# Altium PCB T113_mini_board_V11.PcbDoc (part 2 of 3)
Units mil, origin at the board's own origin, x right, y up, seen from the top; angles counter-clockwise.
Board outline 2716.54 x 2716.54 mil, 4 copper layers (Top Layer, GND, PWR, Bottom Layer); 97 components, 127 nets, 497 pads, 287 vias.
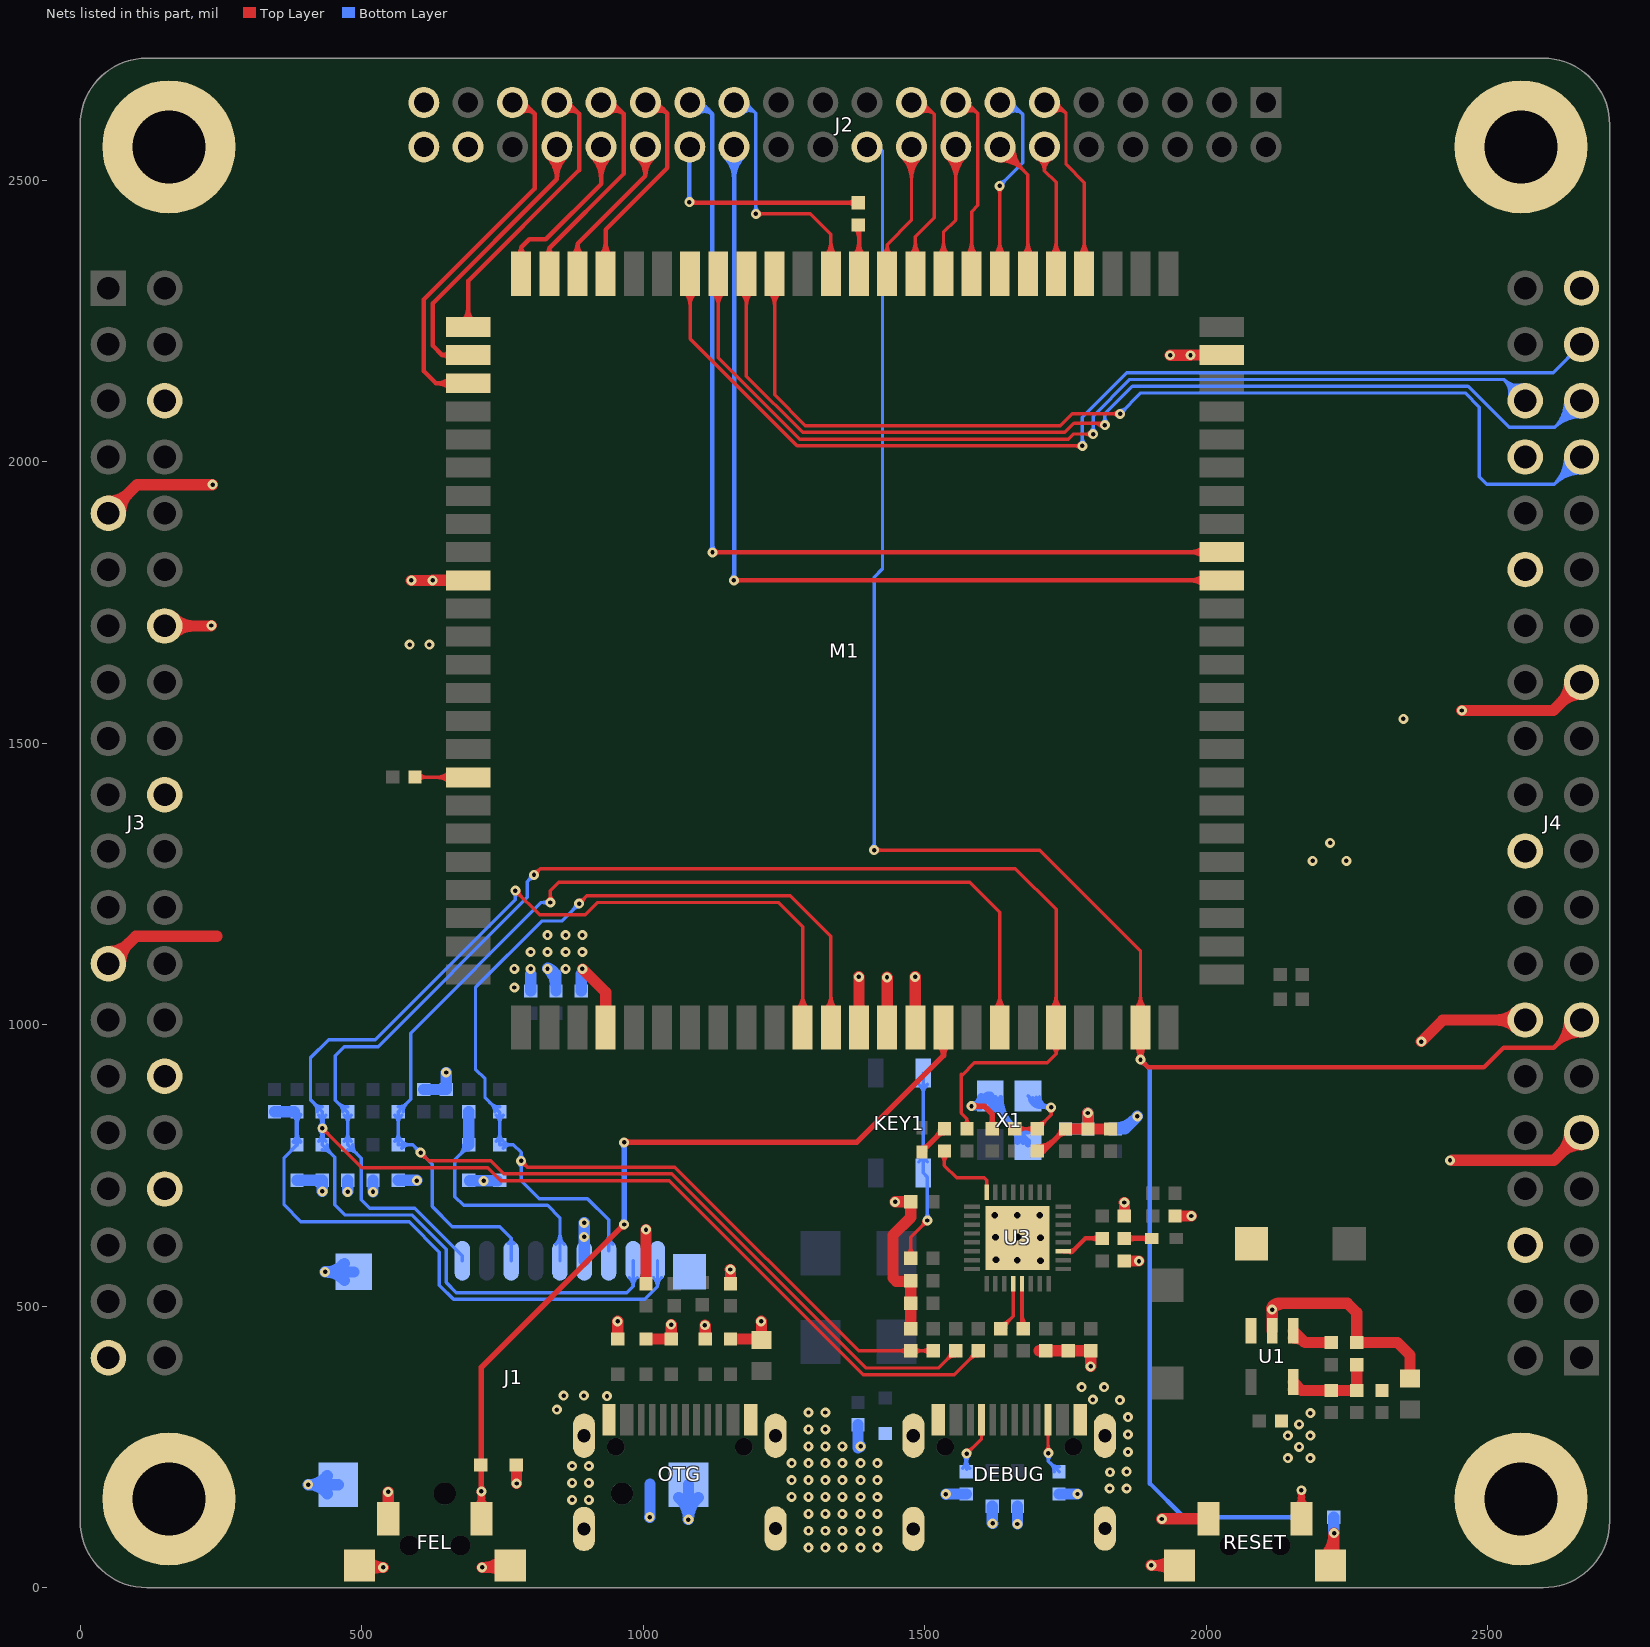
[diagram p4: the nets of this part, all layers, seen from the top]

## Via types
v1: diameter 17.72, hole 7.87, Top Layer to Bottom Layer, tented both sides, 278 vias
v2: diameter 23.62, hole 11.81, Top Layer to Bottom Layer, tented both sides, 9 vias

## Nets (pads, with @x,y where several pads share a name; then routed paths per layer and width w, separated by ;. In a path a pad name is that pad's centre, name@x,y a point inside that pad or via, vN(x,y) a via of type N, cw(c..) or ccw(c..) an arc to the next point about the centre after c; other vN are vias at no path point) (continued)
FEL: D4.2 FEL.2 M1.16 | length 1749.1
  Top Layer w10: FEL.2@702.21,142.47 ccw(c677.14,167.54) 712.59,167.54 ccw(c748.04,167.54) FEL.2@722.98,142.47 ; v1@709.25,169.07 cw(c698.54,162.89) 710.49,159.68 ; v1@709.86,168.27 cw(c703.28,161.69) 712.59,161.69 cw(c721.91,161.69) v1@715.32,168.27 ; v1@709.86,173.73 ccw(c703.28,180.31) 712.59,180.31 ccw(c721.91,180.31) v1@715.32,173.73 ; FEL.2@712.59,122.25 v1(712.59,171) 712.59,391.59 v1(966,645) ; 714.7,159.68 cw(c726.64,162.89) v1@715.93,169.07 ; v1@962.14,645 cw(c952.83,645) 959.41,638.41 cw(c966,631.83) v1@966,641.14 ; v1(966,791) 1379,791 1533.27,945.27 ; v1@968.73,788.27 cw(c975.31,781.69) 975.31,791 cw(c975.31,800.31) v1@968.73,793.73 ; M1.16@1524.9,963.69 cw(c1508.8,945.27) 1533.27,945.27 ; M1.16@1533.27,994.92 1533.27,945.27 ; M1.16@1541.63,963.69 ccw(c1557.73,945.27) 1533.27,945.27
  Bottom Layer w10: 704.03,125.03 ccw(c683.35,145.71) 712.59,145.71 ; 708.84,120.21 712.59,123.96 v1(712.59,171) ; v1@709.86,168.27 cw(c703.28,161.69) 712.59,161.69 cw(c721.91,161.69) v1@715.32,168.27 ; v1@963.27,647.73 ccw(c956.69,654.31) 966,654.31 ccw(c975.31,654.31) v1@968.73,647.73 ; v1@963.27,788.27 cw(c956.69,781.69) 966,781.69 cw(c975.31,781.69) v1@968.73,788.27 ; v1(966,645) v1(966,791)
GND: C1.1 C2.1 C3.1 C4.1 C6.1 C7.1 C8.1 C15.2 C16.2 C17.1 C18.1 C19.1 C20.1 C21.1 C22.1 C23.1 C24.1 C25.1 C26.1 C27.1 C28.1 C29.1 C30.1 C31.1 C32.1 C33.1 D4.1 D5.1 D6.1 D7.1 D8.1 D12.1 D13.1 D14.1 D15.1 D16.1 D17.1 D18.1 D19.1 D20.1 D21.1 D22.1 D23.1 DEBUG.A1B12 DEBUG.B1A12 DEBUG.SHELL FEL.1 FEL.3 FEL.4 J1.6 J1.10 J1.11 J1.12 J1.13 J2.38 J2.39 J2.40 J3.6 J3.9 J3.14 J3.20 J3.25 J3.30 J3.34 J3.39 J4.6 J4.9 J4.14 J4.20 J4.25 J4.30 J4.34 J4.39 M1.4 M1.13 M1.14 M1.15 M1.47 M1.82 OTG.A1B12 OTG.B1A12 OTG.SHELL pad.0 R6.2 R12.1 R13.1 R23.2 R24.2 R38.1 R39.2 RESET.1 RESET.3 RESET.4 U1.2 U3.33 X1.2 X1.4 | length 6477.8
  Top Layer w10: v1@1579.58,855.33 v1(1583,855.33) 1605.67,855.33 1619.92,841.08 C33.1@1619.92,814.99 ; v1@1585.73,852.6 cw(c1592.31,846.01) 1592.31,855.33 cw(c1592.31,864.64) v1@1585.73,858.05 ; C33.1@1615.1,819.8 ccw(c1603.48,831.43) 1619.92,831.43 ccw(c1636.36,831.43) C33.1@1624.74,819.8 ; U3.33@1664.93,621.15 v2(1664.93,622.74) ; C32.1@1699.92,772.43 ccw(c1699.92,791.15) 1713.16,777.91 ; C32.1@1699.92,775.62 1710.87,775.62 C27.1@1749.92,814.67 ; C32.1@1699.92,782.43 ccw(c1699.92,825.3) 1730.23,794.98 ; C27.1@1743.11,814.67 cw(c1726.67,814.67) 1738.29,803.05 cw(c1749.92,791.42) C27.1@1749.92,807.86
  Top Layer w20: J3.25@50,1108.27 98.73,1157 243,1157 ; J3.25@50,1129.76 ccw(c50,1181.66) 86.7,1144.96 ccw(c123.39,1108.27) J3.25@71.5,1108.27 ; J3.9@50,1908.27 100.73,1959 v1(235,1959) ; J3.9@50,1929.76 ccw(c50,1981.66) 86.7,1944.96 ccw(c123.39,1908.27) J3.9@71.5,1908.27 ; J3.14@150,1708.27 232.27,1708.27 v1(233,1709) ; J3.14@165.2,1693.07 cw(c201.9,1656.37) 201.9,1708.27 cw(c201.9,1760.16) J3.14@165.2,1723.47 ; FEL.3@491.48,35.96 v1@537.96,35.96 ; FEL.3@508.48,26.17 cw(c532.12,2.52) v1@532.12,35.96 ; FEL.3@509.79,49.53 ccw(c537.96,71.98) v1@537.96,35.96 ; v1(538,36) v1@537.96,35.96 ; FEL.1@540.38,138.94 ccw(c523.85,155.47) 547.23,155.47 ccw(c570.61,155.47) FEL.1@554.08,138.94 ; v1(547,170) 547.23,169.77 FEL.1@547.23,122.25 ; v1(588,1789) v1(626,1789) 626.21,1789.21 M1.82@688.98,1789.21 ; M1.82@661.87,1783.76 ccw(c648.69,1770.58) 648.69,1789.21 ccw(c648.69,1807.84) M1.82@661.87,1794.67 ; v1(714,36) 714.04,35.96 FEL.4@759.2,35.96 ; v1@715.06,35.96 ccw(c715.06,87.3) FEL.4@751.37,51 ; 727.72,35.96 cw(c727.72,2.52) FEL.4@751.37,26.17 ; v1(775,185) D4.1@775,217.5 ; v1(892,1099) 933.27,1057.73 M1.4@933.27,994.92 ; M1.4@927.81,1022.03 ccw(c914.64,1035.2) 933.27,1035.2 ccw(c951.9,1035.2) M1.4@938.72,1022.03 ; v1(954.58,473.09) 954.92,472.75 D6.1@954.92,441.8 ; D12.1@1004.92,441.8 D7.1@1049.92,441.8 1049.92,466.75 v1(1049.58,467.09) ; R12.1@1004.92,539.99 v1(1004.92,635.92) ; v1(1109.58,466.09) 1109.92,465.75 D8.1@1109.92,441.8 ; v1(1154.58,565.09) 1154.92,564.75 R13.1@1154.92,539.99 ; D13.1@1154.92,441.8 1207.82,441.8 C8.1@1209.88,439.74 1209.88,472.8 v1(1209.58,473.09) ; 1189.06,441.8 cw(c1189.06,420.89) C8.1@1203.84,435.67 ; M1.13@1377.81,1022.03 ccw(c1364.64,1035.2) 1383.27,1035.2 ccw(c1401.9,1035.2) M1.13@1388.72,1022.03 ; v1(1383,1085) 1383.27,1084.73 M1.13@1383.27,994.92 ; M1.14@1427.81,1022.03 ccw(c1414.64,1035.2) 1433.27,1035.2 ccw(c1451.9,1035.2) M1.14@1438.72,1022.03 ; v1(1433,1084) 1433.27,1083.73 M1.14@1433.27,994.92 ; v1(1447.58,685.09) 1447.8,685.3 C22.1@1475.24,685.3 1475.24,657.74 1443.58,626.09 1443.58,550.09 1449.58,544.09 1474.02,544.09 R39.2@1475.24,545.3 C24.1@1475.24,505.3 1474.92,504.99 R38.1@1474.92,459.99 ; M1.15@1477.81,1022.03 ccw(c1464.64,1035.2) 1483.27,1035.2 ccw(c1501.9,1035.2) M1.15@1488.72,1022.03 ; v1(1483,1085) 1483.27,1084.73 M1.15@1483.27,994.92 ; 1702.73,420.62 C18.1@1714.92,420.62 C20.1@1754.92,420.62 C23.1@1794.92,420.62 1794.92,393.43 v1(1794.58,393.09) ; C27.1@1749.92,814.67 C30.1@1789.92,814.67 ; v1(1789.58,843.09) 1789.92,842.75 C30.1@1789.92,814.67 ; C25.1@1829.92,814.67 C30.1@1789.92,814.67 ; C17.1@1854.61,580.3 1880.37,580.3 v1(1880.58,580.09) ; C19.1@1854.61,660.3 v1@1854.61,684.07 ; v1@1902,40 v1(1902.44,39.56) RESET.3@1952.75,39.56 ; v1(1921,122) 1921.24,122.24 RESET.1@2003.92,122.24 ; v1(1936,2189) v1(1972,2189) 1972.21,2189.21 M1.47@2027.56,2189.21 ; RESET.3@1940.34,27.15 ccw(c1910.36,-2.83) 1910.36,39.56 ccw(c1910.36,81.95) RESET.3@1940.34,51.98 ; C31.1@1944.61,660.3 1973.37,660.3 v1(1973.58,660.09) ; RESET.1@1997.08,115.39 ccw(c1980.54,98.86) 1980.54,122.24 ccw(c1980.54,145.62) RESET.1@1997.08,129.09 ; M1.47@2000.45,2183.76 ccw(c1987.28,2170.58) 1987.28,2189.21 ccw(c1987.28,2207.84) M1.47@2000.45,2194.67 ; v1@2115.87,494.12 cw(c2128,492.79) 2128,505 ; v1@2116.19,494.81 cw(c2140.8,470.2) 2140.8,505 ; U1.2@2117.21,456.08 2117.21,493.79 v1(2117,494) 2128,505 ; RESET.4@2208.32,53.22 ccw(c2166.36,97) v1(2227,97) 2227,46.09 RESET.4@2220.47,39.56 ; C6.1@2362,371.56 2362,413 2339.65,435.35 R6.2@2267.21,435.35 2267.21,488.79 2251,505 2128,505 ; v1(2382,970) 2420.27,1008.27 J4.14@2566.54,1008.27 ; v1@2437,759 2617.27,759 J4.9@2666.54,808.27 ; v1(2454,1558) 2616.27,1558 J4.25@2666.54,1608.27 ; J4.14@2551.34,993.07 ccw(c2514.64,956.37) 2514.64,1008.27 ccw(c2514.64,1060.16) J4.14@2551.34,1023.47 ; J4.9@2645.04,808.27 cw(c2593.14,808.27) 2629.84,771.57 cw(c2666.54,734.88) J4.9@2666.54,786.77 ; J4.25@2645.04,1608.27 cw(c2593.14,1608.27) 2629.84,1571.57 cw(c2666.54,1534.88) J4.25@2666.54,1586.77
  Bottom Layer w10: X1.4@1616.45,851.05 cw(c1616.45,828.91) 1632.11,844.57 ; X1.4@1616.45,860.22 1683.38,793.29 X1.2@1683.38,787 ; X1.4@1625.07,869.67 ccw(c1668.71,869.67) 1637.85,838.82 ; X1.4@1635.07,869.67 ccw(c1702.85,869.67) 1654.92,821.75 ; 1649.92,826.75 cw(c1614.11,790.93) X1.2@1664.76,790.93 ; 1655.62,821.05 ccw(c1683.38,848.82) X1.2@1683.38,809.55 ; X1.2@1666.99,809.68 cw(c1648.25,790.93) X1.2@1674.76,790.93
  Bottom Layer w15: v1@1583,856.68 ccw(c1583,896.58) X1.4@1611.21,868.37 ; X1.4@1600.4,871.17 cw(c1583,872.8) v1(1583,855.33) 1598.17,855.33 1613.19,870.35 X1.4@1616.45,873.61
  Bottom Layer w20: D14.1@385,723.5 D17.1@430,723.5 v1(430,704) ; v1(405,183) v1@405.09,182.91 ; v1(435,561) v1@435.14,560.86 ; J1.13@438.55,166.93 ccw(c405.09,139.89) v1@405.09,182.91 ; J1.13@438.55,198.9 cw(c405.09,225.93) v1@405.09,182.91 ; J1.13@458.34,182.91 v1@405.09,182.91 ; J1.11@469.26,545.75 ccw(c435.14,514.78) v1@435.14,560.86 ; J1.11@469.26,575.97 cw(c435.14,606.95) v1@435.14,560.86 ; v1@475,704 D16.1@475,723.5 ; J1.11@485.91,560.86 v1@435.14,560.86 ; v1(520,703) D15.1@520,723.5 ; D19.1@565,723.5 597.5,723.5 v1(598,723) ; C16.2@610,884.69 C15.2@650,884.69 v1(650,915) ; D20.1@691.34,722.72 v1(716.34,722.72) D18.1@741.34,722.72 ; C1.1@800,1059.68 800,1090 ; v1@830.26,1100.11 cw(c825.89,1081.51) 845,1081.51 ; v1@830.81,1099.81 cw(c796.54,1065.54) C3.1@845,1065.54 ; C3.1@845,1059.68 845,1090 ; C2.1@890,1059.68 890,1090 ; v1(895,648) 895,628 895.36,627.64 J1.6@895.36,580.55 ; v1(1011.58,125.09) 1011.92,125.43 1011.92,184 ; J1.12@1063.27,160.17 cw(c1027.95,121.4) v1@1080.4,121.4 ; v1(1080,121) v1@1080.4,121.4 ; J1.12@1080.4,182.91 v1@1080.4,121.4 ; J1.12@1097.53,160.17 ccw(c1132.85,121.4) v1@1080.4,121.4 ; v1@1381.58,248.09 C21.1@1381.58,289.41 ; 1381.58,258.91 ccw(c1393.91,258.91) v1@1385.19,250.19 ; v1@1384,253 v1(1386,251) ; v1(1537.58,166.09) 1537.9,166.41 R24.2@1573.58,166.41 ; X1.4@1612.45,871.09 X1.4@1613.19,870.35 ; D23.1@1619.92,144.59 1619.92,114.75 v1(1620.58,114.09) ; v1(1664.58,113.09) 1664.92,113.43 D22.1@1664.92,144.59 ; R23.2@1738.58,166.41 v1(1771.27,166.41) ; C28.1@1749.92,814.67 C29.1@1789.92,814.67 1789.92,842.75 v1(1789.58,843.09) ; C26.1@1838.58,814.78 1855.27,814.78 v1(1877.58,837.09) ; C26.1@1838.58,816.59 ccw(c1838.58,861.24) 1870.16,829.66 ; D5.1@2226.5,125 2226.5,97.5 v1(2227,97)
  other v1: 1293.58,71.09 1323.58,71.09 1353.58,71.09 1386,71 1416,71 1293.58,101.09 1323.58,101.09 1353.58,101.09 1386,101 1416,101 1293.58,131.09 1323.58,131.09 1353.58,131.09 1386,131 1416,131 873.58,156.09 903.58,156.09 1263.58,161.09 1293.58,161.09 1323.58,161.09 1353.58,161.09 1386,161 1416,161 1828.58,176.09 1858.58,176.09 873.58,186.09 903.58,186.09 1263.58,191.09 1293.58,191.09 1323.58,191.09 1353.58,191.09 1386,191 1416,191 1829,205 1858.58,206.09 873.58,216.09 903.58,216.09 1263.58,221.09 1293.58,221.09 1323.58,221.09 1353.58,221.09 1386,221 1416,221 2145,230 2185,230 1861,241 2165,250 1293.58,251.09 1323.58,251.09 1353.58,251.09 2145,270 2185,270 1861,272 1293.58,281.09 1323.58,281.09 2165,290 1861,303 2185,310 1293.58,311.09 1323.58,311.09 846.58,316.09 1846.58,333.09 1798.58,334.09 935.58,340.09 858.58,341.09 894.58,341.09 1778.58,356.09 1818.58,356.09 895,623 1854.58,684.09 475,703 2433,759 771,1066 771,1099 800,1099 830,1099 862,1099 800,1129 830,1129 862,1129 892,1129 830,1159 862,1159 892,1159 2189,1291 2249,1291 2220,1323 2350,1543 585,1675 620,1675
  other v2: 1705.58,580.67 1664.58,581.67 1626.58,582.67 1625.58,622.09 1705.58,621.67 1624.58,661.67 1664.58,661.67 1704.58,661.67
HPOUTFB: J2.35 M1.75 | length 810.8
  Top Layer w8: M1.75@657.62,2129.51 ccw(c634.21,2106.1) 634.21,2139.21 ccw(c634.21,2172.33) M1.75@657.62,2148.91 ; M1.75@688.98,2139.21 631.79,2139.21 610,2161 610,2288 807,2485 807,2618.19 ; J2.35@767.71,2657.48 807,2618.19 ; J2.35@772.47,2631.92 cw(c782.81,2619.14) 794.43,2630.76 ; J2.35@777.5,2625.7 cw(c788.43,2612.2) 800.71,2624.48 ; J2.35@782.54,2619.48 cw(c794.05,2605.25) 807,2618.2
HPOUTL: J2.34 M1.74 | length 712.4
  Top Layer w8: M1.74@655.58,2182.12 ccw(c643,2174.51) 643,2189.21 ; M1.74@655.58,2196.31 cw(c643,2203.92) 643,2189.21 ; M1.74@688.98,2189.21 643,2189.21 ; J2.34@829.8,2542.4 cw(c789.58,2502.18) 846.45,2502.18 cw(c903.33,2502.18) J2.34@863.11,2542.4 ; J2.34@835.45,2548.05 cw(c808.89,2521.49) 846.45,2521.49 cw(c884.02,2521.49) J2.34@857.46,2548.05 ; J2.34@846.45,2578.74 J2.34@846.45,2559.06 846.45,2501.45 626,2281 626,2206.21 643,2189.21
HPOUTR: J2.33 M1.73 | length 635.8
  Top Layer w8: M1.73@679.28,2248.91 ccw(c655.86,2272.33) 688.98,2272.33 ccw(c722.09,2272.33) M1.73@698.68,2248.91 ; M1.73@688.98,2249 688.98,2320.98 886,2518 886,2617.93 ; J2.33@846.45,2657.48 886,2617.93 ; J2.33@851.16,2631.88 cw(c861.53,2618.83) 873.32,2630.62 ; J2.33@856.14,2625.62 cw(c867.15,2611.76) 879.66,2624.28 ; J2.33@861.11,2619.35 cw(c872.76,2604.7) 886,2617.94
JTAG_TCK: D16.2 J1.1 M1.20 R19.2 R33.1 | length 2832.8
  Top Layer w6: v1(806,1266) 817,1277 1661,1277 1733.27,1204.73 M1.20@1733.27,994.92 1733.27,948 ; v1@806,1271.86 ccw(c806,1286) 816,1276 ccw(c826,1266) v1@811.86,1266 ; 1565,912 1566.5,910.5 ; R33.1@1569.49,821.93 ccw(c1560.76,833.08) 1574.92,833.08 ; R33.1@1574.92,814.99 1574.92,833.08 ; R33.1@1580.35,821.93 cw(c1589.09,833.08) 1574.92,833.08 ; M1.20@1722.86,1026.98 ccw(c1697.74,1052.1) 1733.27,1052.1 ccw(c1768.8,1052.1) M1.20@1743.67,1026.98 ; M1.20@1726.01,960.47 cw(c1718.94,948) 1733.27,948 ; M1.20@1727.1,1022.74 ccw(c1712.22,1037.62) 1733.27,1037.62 ccw(c1754.31,1037.62) M1.20@1739.43,1022.74 ; M1.20@1740.53,960.47 ccw(c1747.6,948) 1733.27,948 ; 1566.5,910.5 1588,932 1717.27,932 1733.27,948 ; 1566.5,910.5 1565,909 1565,843 1574.92,833.08
  Bottom Layer w6: 457.67,861.3 ccw(c475,878.63) R19.2@475,854.13 ; 460.91,858.07 cw(c448.15,845.31) R19.2@466.19,845.31 ; D16.2@468.77,792.73 ccw(c453.73,807.77) 475,807.77 ccw(c496.27,807.77) D16.2@481.23,792.73 ; R19.2@468.77,839.08 cw(c453.73,824.04) 475,824.04 cw(c496.27,824.04) R19.2@481.23,839.08 ; D16.2@475,777.68 cw(c475,755.08) 490.98,771.06 ; D16.2@475,786.5 475,843.98 453,865.98 453,945.03 468.97,961 529.12,961 794,1225.88 794,1254 v1(806,1266) ; D16.2@476.34,786.5 476.34,785.71 499,763.05 499,689 514,674 594.06,674 678.82,589.24 J1.1@678.82,580.55 ; D16.2@483.81,786.5 ccw(c503.75,786.5) 489.65,772.4 ; v1@800.14,1266 cw(c786,1266) 796,1256 cw(c806,1246) v1@806,1260.14
JTAG_TDI: D18.2 J1.7 M1.12 R21.2 R34.1 R38.2 | length 2867.7
  Top Layer w6: v1@783,752.14 cw(c783,738) 793,748 cw(c803,758) v1@788.86,758 ; v1(783,758) 794,747 1056,747 1382.38,420.62 R38.2@1474.92,420.62 R34.1@1514.92,420.62 ; v1(886,1215) 900,1229 1261,1229 1333.27,1156.73 M1.12@1333.27,994.92 ; v1@886,1220.86 ccw(c886,1235) 896,1225 ccw(c906,1215) v1@891.86,1215 ; M1.12@1322.86,1026.98 ccw(c1297.74,1052.1) 1333.27,1052.1 ccw(c1368.8,1052.1) M1.12@1343.67,1026.98 ; M1.12@1327.1,1022.74 ccw(c1312.22,1037.62) 1333.27,1037.62 ccw(c1354.31,1037.62) M1.12@1339.43,1022.74 ; R38.2@1468.69,414.39 ccw(c1453.65,399.35) 1453.65,420.62 ccw(c1453.65,441.89) R38.2@1468.69,426.85 ; R38.2@1481.15,414.39 cw(c1496.19,399.35) 1496.19,420.62 cw(c1496.19,441.89) R38.2@1481.15,426.85 ; R34.1@1508.69,414.39 ccw(c1493.65,399.35) 1493.65,420.62 ccw(c1493.65,441.89) R34.1@1508.69,426.85
  Bottom Layer w6: 727.67,861.3 ccw(c745,878.63) R21.2@745,854.13 ; 730.91,858.07 cw(c718.15,845.31) R21.2@736.19,845.31 ; D18.2@738.77,792.73 ccw(c723.73,807.77) 745,807.77 ccw(c766.27,807.77) 751.23,792.73 ccw(c766.27,807.77) 766.27,786.5 ccw(c766.27,765.22) D18.2@751.23,780.27 ; R21.2@738.77,839.08 cw(c723.73,824.04) 745,824.04 cw(c766.27,824.04) R21.2@751.23,839.08 ; v1@778.86,753.86 cw(c768.86,743.86) 783,743.86 cw(c797.14,743.86) v1@787.14,753.86 ; v1@778.86,762.14 ccw(c768.86,772.14) 783,772.14 ccw(c797.14,772.14) v1@787.14,762.14 ; v1@880.14,1215 cw(c866,1215) 876,1205 cw(c886,1195) v1@886,1209.14 ; v1(886,1215) 855,1184 820,1184 702,1066 702,921 719,904 719,869.98 745,843.98 D18.2@745,786.5 769.5,786.5 783,773 v1(783,758) 783,723 815,691 901,691 938.66,653.34 J1.7@938.66,598 ; J1.7@931.04,609.83 ccw(c912.63,628.23) 938.66,628.23 ccw(c964.68,628.23) J1.7@946.28,609.83
JTAG_TDO: D19.2 J1.3 M1.18 R22.2 R35.1 | length 3468.3
  Top Layer w6: v1@604.5,766.64 cw(c604.5,752.5) 614.5,762.5 cw(c624.5,772.5) v1@610.36,772.5 ; v1(604.5,772.5) 619,758 729,758 737.99,749.01 ; 737.97,749 751.97,735 1050.97,735 1395.88,390.09 1524.39,390.09 R35.1@1554.92,420.62 ; v1@830.86,1221.14 ccw(c820.86,1231.14) 835,1231.14 ccw(c849.14,1231.14) v1@839.14,1221.14 ; v1(835,1217) 835,1238 850,1253 1580,1253 1633.27,1199.73 M1.18@1633.27,994.92 M1.18@1633,994.65 ; R35.1@1546.11,420.62 cw(c1524.84,420.62) 1539.88,405.58 cw(c1554.92,390.54) R35.1@1554.92,411.81 ; M1.18@1622.86,1026.98 ccw(c1597.74,1052.1) 1633.27,1052.1 ccw(c1668.8,1052.1) M1.18@1643.67,1026.98 ; M1.18@1627.1,1022.74 ccw(c1612.22,1037.62) 1633.27,1037.62 ccw(c1654.31,1037.62) M1.18@1639.43,1022.74
  Bottom Layer w6: D19.2@558.77,792.73 ccw(c543.73,807.77) 565,807.77 ccw(c586.27,807.77) 571.23,792.73 ccw(c586.27,807.77) 586.27,786.5 ccw(c586.27,765.22) D19.2@571.23,780.27 ; R22.2@558.77,839.08 cw(c543.73,824.04) 565,824.04 cw(c586.27,824.04) R22.2@571.23,839.08 ; R22.2@565,845.31 587,867.31 587,984.94 819.06,1217 v1(835,1217) ; R22.2@565,854.13 ccw(c565,875.4) 580.04,860.36 ccw(c595.08,845.31) R22.2@573.81,845.31 ; R22.2@566.34,845.31 565,843.98 D19.2@565,786.5 590.5,786.5 v1(604.5,772.5) 625,752 625,677 661,641 745,641 765.43,620.57 ; v1@598.64,772.5 ccw(c584.5,772.5) 594.5,782.5 ccw(c604.5,792.5) v1@604.5,778.36 ; v1@604.5,766.64 cw(c604.5,752.5) 614.5,762.5 cw(c624.5,772.5) v1@610.36,772.5 ; J1.3@760.17,611.62 ccw(c755.18,620.57) 765.43,620.57 ; J1.3@765.43,580.55 765.43,620.57 ; J1.3@770.68,611.62 cw(c775.68,620.57) 765.43,620.57 ; v1@830.86,1212.86 ccw(c820.86,1202.86) 820.86,1217 ccw(c820.86,1231.14) v1@830.86,1221.14
JTAG_TMS: D17.2 J1.8 M1.11 R20.2 R36.1 | length 4026
  Top Layer w6: v1@430,810.14 cw(c430,796) 440,806 cw(c450,816) v1@435.86,816 ; v1(430,816) 500,746 724,746 747,723 1046,723 1390.91,378.09 1552.39,378.09 R36.1@1594.92,420.62 ; v1@773,1232.14 cw(c773,1218) 783,1228 cw(c793,1238) v1@778.86,1238 ; v1(773,1238) 816,1195 897,1195 919,1217 1240,1217 1283.27,1173.73 M1.11@1283.27,994.92 ; M1.11@1272.86,1026.98 ccw(c1247.74,1052.1) 1283.27,1052.1 ccw(c1318.8,1052.1) M1.11@1293.67,1026.98 ; M1.11@1277.1,1022.74 ccw(c1262.22,1037.62) 1283.27,1037.62 ccw(c1304.31,1037.62) M1.11@1289.43,1022.74 ; R36.1@1586.11,420.62 cw(c1564.84,420.62) 1579.88,405.58 cw(c1594.92,390.54) R36.1@1594.92,411.81
  Bottom Layer w6: R20.2@421.19,845.31 ccw(c399.92,845.31) 414.96,860.36 ccw(c430,875.4) R20.2@430,854.13 ; D17.2@423.77,792.73 ccw(c408.73,807.77) 430,807.77 ccw(c451.27,807.77) D17.2@436.23,792.73 ; R20.2@423.77,839.08 cw(c408.73,824.04) 430,824.04 cw(c451.27,824.04) R20.2@436.23,839.08 ; v1@425.53,812.22 cw(c415.81,803.99) 428.11,800.7 ; v1@425.53,819.78 ccw(c415.9,827.93) 428.08,831.2 ; v1@425.86,811.86 cw(c415.86,801.86) 430,801.86 cw(c444.14,801.86) v1@434.14,811.86 ; v1@425.86,820.14 ccw(c415.86,830.14) 430,830.14 ccw(c444.14,830.14) v1@434.14,820.14 ; v1@427.07,810.93 cw(c423.64,804.98) 430.27,806.76 ; v1@427.07,821.07 ccw(c423.55,827.17) 430.35,825.35 ; 429.65,825.35 ccw(c436.45,827.17) v1@432.93,821.07 ; 429.73,806.76 cw(c436.36,804.98) v1@432.93,810.93 ; D17.2@430,777.68 cw(c430,756.41) 445.04,771.45 cw(c460.08,786.5) D17.2@438.81,786.5 ; 431.89,800.7 cw(c444.19,803.99) v1@434.47,812.22 ; 431.92,831.2 ccw(c444.1,827.93) v1@434.47,819.78 ; v1@768.86,1233.86 cw(c758.86,1223.86) 773,1223.86 cw(c787.14,1223.86) v1@777.14,1233.86 ; v1(773,1238) 773,1221.85 524.15,973 441,973 409,941 409,866.31 R20.2@430,845.31 v1(430,816) D17.2@430,786.5 452,764.5 452,680 470,662 589.09,662 650,601.09 650,542 668,524 971,524 981.97,534.97 ; J1.8@974.83,550.82 cw(c960.8,534.97) 981.97,534.97 ; J1.8@981.97,580.55 981.97,534.97 ; J1.8@989.11,550.82 ccw(c1003.13,534.97) 981.97,534.97
LCD_D14: J2.11 M1.52 | length 522.5
  Top Layer w6: J2.11@1712.6,2657.48 1751,2619.08 ; J2.11@1721.04,2628.49 cw(c1731.3,2617.19) 1742.09,2627.98 ; J2.11@1725.07,2624.05 cw(c1735.53,2612.52) 1746.55,2623.53 ; J2.11@1729.1,2619.61 cw(c1739.77,2607.85) 1751,2619.08 ; J2.11@1737.16,2637.8 ccw(c1748.92,2637.8) 1740.6,2629.47 ; M1.52@1772.86,2365.56 ccw(c1747.74,2390.69) 1783.27,2390.69 ccw(c1818.8,2390.69) M1.52@1793.67,2365.56 ; M1.52@1777.1,2361.32 ccw(c1762.22,2376.2) 1783.27,2376.2 ccw(c1804.31,2376.2) M1.52@1789.43,2361.32 ; M1.52@1783.27,2333.5 1783.27,2495.73 1751,2528 1751,2619.08
LCD_D15: J2.12 M1.53 | length 412.6
  Top Layer w6: J2.12@1700.38,2537.75 cw(c1688.31,2516.67) 1712.6,2516.67 ; J2.12@1703.37,2542.95 cw(c1694.24,2527.03) 1712.6,2527.03 cw(c1730.95,2527.03) J2.12@1721.83,2542.95 ; J2.12@1712.6,2559.06 1712.6,2516.67 ; M1.53@1722.86,2365.56 ccw(c1697.74,2390.69) 1733.27,2390.69 ccw(c1768.8,2390.69) M1.53@1743.67,2365.56 ; J2.12@1724.81,2537.75 ccw(c1736.89,2516.67) 1712.6,2516.67 ; M1.53@1727.1,2361.32 ccw(c1712.22,2376.2) 1733.27,2376.2 ccw(c1754.31,2376.2) M1.53@1739.43,2361.32 ; M1.53@1733.27,2333.5 1733.27,2496 1712.6,2516.67
LCD_D18: J2.13 M1.55 | length 578.5
  Top Layer w6: M1.55@1622.86,2365.56 ccw(c1597.74,2390.69) 1633.27,2390.69 ccw(c1668.8,2390.69) M1.55@1643.67,2365.56 ; M1.55@1627.1,2361.32 ccw(c1612.22,2376.2) 1633.27,2376.2 ccw(c1654.31,2376.2) M1.55@1639.43,2361.32 ; v1@1628.86,2485.86 cw(c1618.21,2475.21) 1633.27,2475.21 ; v1(1633,2490) 1633.27,2489.73 M1.55@1633.27,2333.5 ; 1633.27,2476.5 cw(c1646.5,2476.5) v1@1637.14,2485.86
  Bottom Layer w6: v1(1633,2490) 1674,2531 1674,2617.34 ; v1@1633,2495.86 ccw(c1633,2510) 1643,2500 ccw(c1653,2490) v1@1638.86,2490 ; J2.13@1633.86,2657.48 1674,2617.34 ; J2.13@1641.73,2628.01 cw(c1652.46,2614.7) 1664.55,2626.79 ; J2.13@1645.5,2623.34 cw(c1656.67,2609.46) 1669.27,2622.06 ; J2.13@1649.26,2618.67 cw(c1660.89,2604.23) 1674,2617.34 ; J2.13@1658.42,2637.8 ccw(c1670.18,2637.8) 1661.86,2629.47
LCD_D19: J2.14 M1.54 | length 546
  Top Layer w6: J2.14@1633.86,2534.5 cw(c1633.86,2475.21) 1675.78,2517.13 cw(c1717.71,2559.06) J2.14@1658.42,2559.06 ; J2.14@1633.86,2540.5 cw(c1633.86,2495.69) 1665.54,2527.37 cw(c1697.22,2559.06) J2.14@1652.42,2559.06 ; J2.14@1633.86,2546.5 cw(c1633.86,2516.18) 1655.3,2537.62 cw(c1676.74,2559.06) J2.14@1646.42,2559.06 ; J2.14@1633.86,2559.06 1683.27,2509.64 M1.54@1683.27,2333.5 ; M1.54@1672.86,2365.56 ccw(c1647.74,2390.69) 1683.27,2390.69 ccw(c1718.8,2390.69) M1.54@1693.67,2365.56 ; M1.54@1677.1,2361.32 ccw(c1662.22,2376.2) 1683.27,2376.2 ccw(c1704.31,2376.2) M1.54@1689.43,2361.32
LCD_D20: J2.15 M1.56 | length 515.7
  Top Layer w6: J2.15@1555.12,2657.48 1594,2618.6 ; J2.15@1563.4,2628.36 cw(c1573.8,2616.51) 1584.94,2627.65 ; J2.15@1567.36,2623.85 cw(c1578.03,2611.69) 1589.47,2623.13 ; J2.15@1571.32,2619.34 cw(c1582.26,2606.86) 1594,2618.6 ; M1.56@1572.86,2365.56 ccw(c1547.74,2390.69) 1583.27,2390.69 ccw(c1618.8,2390.69) M1.56@1593.67,2365.56 ; M1.56@1577.1,2361.32 ccw(c1562.22,2376.2) 1583.27,2376.2 ccw(c1604.31,2376.2) M1.56@1589.43,2361.32 ; J2.15@1579.68,2637.8 ccw(c1591.44,2637.8) 1583.12,2629.47 ; M1.56@1583.27,2333.5 1583.27,2444.27 1594,2455 1594,2618.6
LCD_D21: J2.16 M1.57 | length 554.3
  Top Layer w6: M1.57@1522.86,2365.56 ccw(c1497.74,2390.69) 1533.27,2390.69 ccw(c1568.8,2390.69) M1.57@1543.67,2365.56 ; M1.57@1527.1,2361.32 ccw(c1512.22,2376.2) 1533.27,2376.2 ccw(c1554.31,2376.2) M1.57@1539.43,2361.32 ; M1.57@1533.27,2333.5 1533.27,2407.27 1555.12,2429.12 J2.16@1555.12,2578.74 ; J2.16@1537.75,2541.69 cw(c1495.83,2499.76) 1555.12,2499.76 cw(c1614.41,2499.76) J2.16@1572.48,2541.69 ; J2.16@1541.99,2545.93 cw(c1510.31,2514.25) 1555.12,2514.25 cw(c1599.92,2514.25) J2.16@1568.24,2545.93 ; J2.16@1546.24,2550.17 cw(c1524.8,2528.74) 1555.12,2528.74 cw(c1585.44,2528.74) J2.16@1564,2550.17
LCD_D22: J2.17 M1.58 | length 533.1
  Top Layer w6: M1.58@1472.86,2365.56 ccw(c1447.74,2390.69) 1483.27,2390.69 ccw(c1518.8,2390.69) M1.58@1493.67,2365.56 ; J2.17@1476.38,2657.48 1517,2616.86 ; M1.58@1477.1,2361.32 ccw(c1462.22,2376.2) 1483.27,2376.2 ccw(c1504.31,2376.2) M1.58@1489.43,2361.32 ; M1.58@1483.27,2333.5 1483.27,2399.27 1517,2433 1517,2616.86 ; J2.17@1484.1,2627.89 cw(c1494.94,2614) 1507.4,2626.46 ; J2.17@1487.79,2623.16 cw(c1499.14,2608.6) 1512.2,2621.66 ; J2.17@1491.48,2618.43 cw(c1503.35,2603.21) 1517,2616.86 ; J2.17@1500.94,2637.8 ccw(c1512.7,2637.8) 1504.38,2629.47
LCD_D23: J2.18 M1.59 | length 542.1
  Top Layer w6: M1.59@1424.23,2366.77 ccw(c1409.83,2385.27) 1433.27,2385.27 ; M1.59@1427.91,2362.04 ccw(c1419.38,2372.99) 1433.27,2372.99 ccw(c1447.15,2372.99) M1.59@1438.62,2362.04 ; M1.59@1433.27,2333.5 1433.27,2385.27 ; M1.59@1442.31,2366.77 cw(c1456.71,2385.27) 1433.27,2385.27 ; J2.18@1459.01,2541.69 cw(c1417.09,2499.76) 1476.38,2499.76 cw(c1535.67,2499.76) J2.18@1493.74,2541.69 ; J2.18@1463.25,2545.93 cw(c1431.57,2514.25) 1476.38,2514.25 cw(c1521.18,2514.25) J2.18@1489.5,2545.93 ; J2.18@1467.5,2550.17 cw(c1446.06,2528.74) 1476.38,2528.74 cw(c1506.7,2528.74) J2.18@1485.26,2550.17 ; J2.18@1476.38,2578.74 1476.38,2428.38 1433.27,2385.27
LCD_DE: J2.25 M1.61 | length 666.4
  Top Layer w6: v1(1200,2440) 1297,2440 1333.27,2403.73 M1.61@1333.27,2333.5 ; v1@1204.14,2435.86 cw(c1214.14,2425.86) 1214.14,2440 cw(c1214.14,2454.14) v1@1204.14,2444.14 ; M1.61@1322.86,2365.56 ccw(c1297.74,2390.69) 1333.27,2390.69 ccw(c1368.8,2390.69) M1.61@1343.67,2365.56 ; M1.61@1327.1,2361.32 ccw(c1312.22,2376.2) 1333.27,2376.2 ccw(c1354.31,2376.2) M1.61@1339.43,2361.32
  Bottom Layer w6: J2.25@1161.42,2657.48 1200,2618.9 ; J2.25@1169.8,2628.44 cw(c1180.11,2616.93) 1191.04,2627.86 ; J2.25@1173.8,2623.97 cw(c1184.35,2612.21) 1195.52,2623.38 ; J2.25@1177.8,2619.5 cw(c1188.58,2607.48) 1200,2618.9 ; J2.25@1185.97,2637.8 ccw(c1197.74,2637.8) 1189.42,2629.47 ; v1@1195.86,2444.14 ccw(c1185.86,2454.14) 1200,2454.14 ccw(c1214.14,2454.14) v1@1204.14,2444.14 ; v1(1200,2440) 1200,2618.9
LCD_HSYNC: J2.27 M1.40 | length 1908.9
  Top Layer w8: v1(1123,1839) 1123.21,1839.21 M1.40@2027.56,1839.21 ; v1@1126.44,1835.56 cw(c1135.24,1826.76) 1135.24,1839.21 ; v1@1126.44,1842.44 ccw(c1134.22,1850.22) 1134.22,1839.21 ; M1.40@1996.21,1829.51 ccw(c1972.79,1806.1) 1972.79,1839.21 ccw(c1972.79,1872.33) M1.40@1996.21,1848.91
  Bottom Layer w8: J2.27@1082.68,2657.48 1123,2617.16 ; J2.27@1087.23,2631.76 cw(c1097.69,2617.88) 1109.99,2630.17 ; J2.27@1092.04,2625.37 cw(c1103.29,2610.46) 1116.49,2623.66 ; J2.27@1096.86,2618.98 cw(c1108.88,2603.04) 1123,2617.16 ; v1@1119.56,1842.44 ccw(c1111.27,1850.73) 1123,1850.73 ccw(c1134.73,1850.73) v1@1126.44,1842.44 ; v1(1123,1839) 1123,2617.16
LCD_PCLK: J2.28 R4.2 | length 479.3
  Top Layer w8: v1(1082,2461) 1083.31,2459.69 R4.2@1382,2459.69 ; v1@1085.44,2464.44 ccw(c1096.9,2475.9) 1096.9,2459.69 ; R4.2@1376.48,2454.16 ccw(c1363.14,2440.83) 1363.14,2459.69 ccw(c1363.14,2478.54) R4.2@1376.48,2465.21
  Bottom Layer w8: v1@1078.56,2464.44 ccw(c1070.27,2472.73) 1082,2472.73 ccw(c1093.73,2472.73) v1@1085.44,2464.44 ; v1(1082,2461) 1082,2578.06 J2.28@1082.68,2578.74
LCD_RESET: D5.2 J2.20 J4.13 M1.23 RESET.2 | length 4618.3
  Top Layer w6: v1(1410,1310) 1704,1310 1883.27,1130.73 M1.23@1883.27,994.92 M1.23@1883.27,988 ; v1@1414.14,1305.86 cw(c1424.14,1295.86) 1424.14,1310 cw(c1424.14,1324.14) v1@1414.14,1314.14 ; M1.23@1872.86,1026.98 ccw(c1847.74,1052.1) 1883.27,1052.1 ccw(c1918.8,1052.1) M1.23@1893.67,1026.98 ; M1.23@1877.1,1022.74 ccw(c1862.22,1037.62) 1883.27,1037.62 ccw(c1904.31,1037.62) M1.23@1889.43,1022.74
  Top Layer w8: M1.23@1873.57,963.57 cw(c1850.15,940.15) 1883.27,940.15 cw(c1916.38,940.15) M1.23@1892.97,963.57 ; v1@1879.06,940.16 ccw(c1867.05,947.1) 1880.45,950.68 ; v1@1879.83,941.17 ccw(c1871.54,949.46) 1883.27,949.46 ccw(c1895,949.46) v1@1886.7,941.17 ; v1@1880.84,941.94 ccw(c1876.04,950.24) 1885.31,947.76 ; 1881.23,947.76 ccw(c1890.49,950.24) v1@1885.7,941.94 ; v1@1883.27,932.87 cw(c1883.27,921.15) 1891.56,929.44 cw(c1899.85,937.73) v1@1888.13,937.73 ; M1.23@1883.27,988 v1(1883.27,937.73) 1897,924 2493,924 2528,959 2617.27,959 J4.13@2666.54,1008.27 ; 1886.09,950.68 ccw(c1899.48,947.1) v1@1887.47,940.16 ; RESET.2@2158.19,143.18 ccw(c2131.42,169.95) 2169.28,169.95 ccw(c2207.15,169.95) RESET.2@2180.38,143.18 ; v1@2164.79,170.57 cw(c2151.49,162.89) 2166.33,158.92 ; v1@2165.56,169.56 cw(c2156.59,160.59) 2169.28,160.59 ; v1@2166.57,168.79 cw(c2161.58,160.16) 2171.22,162.74 ; 2167.66,163.88 cw(c2175.48,161.78) v1@2171.43,168.79 ; v1(2169,173) 2169.28,172.72 RESET.2@2169.28,122.24 ; 2169.28,161.96 cw(c2180.04,161.96) v1@2172.44,169.56 ; 2171.86,160.34 cw(c2184.89,163.83) v1@2173.21,170.57 ; J4.13@2639.04,1008.27 cw(c2572.66,1008.27) 2619.6,961.33 cw(c2666.54,914.39) J4.13@2666.54,980.77 ; J4.13@2647.04,1008.27 cw(c2599.97,1008.27) 2633.25,974.99 cw(c2666.54,941.7) J4.13@2666.54,988.77
  Bottom Layer w6: J2.20@1397.64,2578.74 1425,2551.38 1425,1810 1410,1795 v1(1410,1310) ; v1@1405.86,1314.14 ccw(c1395.86,1324.14) 1410,1324.14 ccw(c1424.14,1324.14) v1@1414.14,1314.14
  Bottom Layer w8: v1@1883.27,932.87 cw(c1883.27,921.15) 1891.56,929.44 cw(c1899.85,937.73) v1@1888.13,937.73 ; v1(1883.27,937.73) 1900,921 1900,185 1960,125 D5.2@2163.5,125 2169,130.5 v1(2169,173) ; D5.2@2157.98,119.48 ccw(c2144.65,106.14) 2144.65,125 ccw(c2144.65,143.86) D5.2@2157.98,130.52 ; v1@2165.56,169.56 cw(c2157.27,161.27) 2169,161.27 cw(c2180.73,161.27) v1@2172.44,169.56
LCD_VSYNC: J2.26 M1.39 | length 1893.6
  Top Layer w8: v1(1161,1789) 1161.21,1789.21 M1.39@2027.56,1789.21 ; v1@1164.44,1785.56 cw(c1173.24,1776.76) 1173.24,1789.21 ; v1@1164.44,1792.44 ccw(c1172.22,1800.22) 1172.22,1789.21 ; M1.39@1996.21,1779.51 ccw(c1972.79,1756.1) 1972.79,1789.21 ccw(c1972.79,1822.33) M1.39@1996.21,1798.91
  Bottom Layer w8: J2.26@1144.76,2542.4 cw(c1104.54,2502.18) 1161.42,2502.18 cw(c1218.29,2502.18) J2.26@1178.07,2542.4 ; J2.26@1150.41,2548.05 cw(c1123.85,2521.49) 1161.42,2521.49 cw(c1198.98,2521.49) J2.26@1172.42,2548.05 ; v1@1157.56,1792.44 ccw(c1148.27,1801.73) 1161.42,1801.73 ; v1@1161.42,1789 J2.26@1161.42,2578.74 ; 1161.42,1799.73 ccw(c1171.73,1799.73) v1@1164.44,1792.44
LED0: R29.1 U3.11 | length 128.9
  Top Layer w8: U3.11@1745.91,597.53 1762.58,597.53 ; U3.11@1755.7,597.49 ccw(c1759.12,600.99) 1762.58,597.53 ; U3.11@1755.75,597.47 ccw(c1755.75,613.82) 1767.31,602.26 ; R29.1@1809.71,614.78 ccw(c1796.38,601.45) 1796.38,620.3 ccw(c1796.38,639.16) R29.1@1809.71,625.83 ; R29.1@1815.24,620.3 1785.35,620.3 1762.58,597.53
LED1: R28.1 U3.24 | length 166.6
  Top Layer w6: R28.1@1528.69,769.39 cw(c1513.65,754.35) 1534.92,754.35 cw(c1556.19,754.35) R28.1@1541.15,769.39 ; R28.1@1534.92,775.62 1534.92,749.75 1556.58,728.09 1605.48,728.09 1609.81,723.76 U3.24@1609.81,702.13
LINEINL: J2.30 M1.70 | length 470.1
  Top Layer w8: M1.70@873.78,2365.07 ccw(c852.55,2387.27) 883.27,2387.27 ; M1.70@883.27,2333.5 883.27,2387.27 ; M1.70@892.75,2365.07 cw(c913.99,2387.27) 883.27,2387.27 ; J2.30@988.63,2541.14 cw(c960.26,2507.94) 1003.94,2507.94 ; J2.30@993.83,2547.23 cw(c975.09,2525.3) 1003.94,2525.3 cw(c1032.78,2525.3) J2.30@1014.04,2547.23 ; J2.30@1003.94,2578.74 J2.30@1003.94,2559.06 1003.94,2507.94 ; J2.30@1019.24,2541.14 ccw(c1047.61,2507.94) 1003.94,2507.94 ; 883.27,2387.27 1003.94,2507.94
LINEINR: J2.29 M1.69 | length 489.3
  Top Layer w8: M1.69@923.57,2364.86 ccw(c900.15,2388.27) 933.27,2388.27 ccw(c966.38,2388.27) M1.69@942.97,2364.86 ; M1.69@933.27,2333.5 933.27,2412.27 1043,2522 1043,2618.42 ; J2.29@1003.94,2657.48 1043,2618.42 ; J2.29@1013.81,2625.77 cw(c1024.67,2612.56) 1036.76,2624.65 ; J2.29@1018.89,2619.59 cw(c1030.3,2605.71) 1043,2618.42
MICIN3N: J2.32 M1.72 | length 503.9
  Top Layer w8: M1.72@775.58,2366.52 ccw(c765.78,2381) 783.27,2381 ; M1.72@783.27,2333.5 783.27,2381 ; M1.72@790.95,2366.52 cw(c800.75,2381) 783.27,2381 ; J2.32@908.54,2542.4 cw(c868.32,2502.18) 925.2,2502.18 cw(c982.07,2502.18) J2.32@941.85,2542.4 ; J2.32@914.19,2548.05 cw(c887.63,2521.49) 925.2,2521.49 cw(c962.76,2521.49) J2.32@936.2,2548.05 ; J2.32@925.2,2578.74 925.2,2493.2 827,2395 797.27,2395 783.27,2381
MICIN3P: J2.31 M1.71 | length 503
  Top Layer w8: M1.71@826.26,2366.95 ccw(c818.94,2379.27) 833.27,2379.27 ; M1.71@833.27,2333.5 833.27,2379.27 ; M1.71@840.28,2366.95 cw(c847.6,2379.27) 833.27,2379.27 ; J2.31@925.2,2657.48 965,2617.68 ; J2.31@929.85,2631.84 cw(c940.25,2618.51) 952.21,2630.47 ; J2.31@934.77,2625.53 cw(c945.86,2611.33) 958.6,2624.07 ; J2.31@939.7,2619.23 cw(c951.47,2604.15) 965,2617.68 ; 833.27,2379.27 965,2511 965,2617.68
NetC5_1: C5.1 R6.1 R7.2 U1.5 | length 180.8
  Top Layer w20: U1.5@2154.43,352.05 cw(c2160.89,341.74) 2169.51,350.35 ; U1.5@2154.61,365.24 2169.51,350.35 ; R6.1@2267.21,395.98 R7.2@2267.21,350.35 2169.51,350.35
NetC32_2: C32.2 R37.1 X1.1 | length 428.2
  Top Layer w6: R37.1@1659.92,814.99 C32.2@1699.92,814.99 1724.58,839.65 ; R37.1@1666.15,808.76 cw(c1681.19,793.72) 1681.19,814.99 cw(c1681.19,836.26) R37.1@1666.15,821.22 ; C32.2@1693.69,808.76 ccw(c1678.65,793.72) 1678.65,814.99 ccw(c1678.65,836.26) C32.2@1693.69,821.22 ; C32.2@1699.92,823.8 ccw(c1699.92,845.07) 1714.96,830.03 ccw(c1730,814.99) C32.2@1708.73,814.99 ; v1@1720.59,848.8 cw(c1712.09,839.65) 1724.58,839.65 ; v1(1724.58,853.09) 1724.58,839.65 ; v1@1728.57,848.8 ccw(c1737.07,839.65) 1724.58,839.65
  Bottom Layer w6: X1.1@1683.38,873.61 1703.9,853.09 v1(1724.58,853.09) cw(c1724.58,873.88) X1.1@1703.9,871.77 ; X1.1@1685.99,869.94 ccw(c1704.65,871.85) X1.1@1704.65,853.09 ; X1.1@1691.96,870.55 ccw(c1711.29,872.53) 1711.29,853.09 ; X1.1@1697.93,871.16 ccw(c1717.94,873.2) v1@1717.94,853.09 ; 1710.76,855.01 ccw(c1713.5,865.24) 1720.63,857.42 cw(c1715.99,862.6) 1714.19,855.88 cw(c1712.38,849.15) v1@1719.01,851.29 ; 1714.49,854.01 cw(c1712.35,846.03) v1@1719.51,850.16 ; v1@1720.44,848.95 ccw(c1710.44,838.95) 1710.44,853.09 ccw(c1710.44,867.23) v1@1720.44,857.23
NetD14_2: D14.2 J1.9 R15.1 R17.2 | length 1129.6
  Bottom Layer w6: D14.2@385,786.5 362,763.5 362,680 392,650 584.12,650 638,596.12 638,537 663,512 1003,512 1025.28,534.28 ; J1.9@1017.97,550.98 cw(c1002.56,534.28) 1025.28,534.28 ; J1.9@1025.28,580.55 1025.28,534.28 ; J1.9@1032.59,550.98 ccw(c1048,534.28) 1025.28,534.28
  Bottom Layer w8: D14.2@379.48,792.02 ccw(c366.14,805.35) 385,805.35 ccw(c403.86,805.35) D14.2@390.52,792.02 ; R17.2@379.48,839.79 cw(c366.14,826.46) 385,826.46 cw(c403.86,826.46) R17.2@390.52,839.79 ; D14.2@385,786.5 R17.2@385,845.31
  Bottom Layer w20: R15.1@345,845.31 R17.2@380,845.31
NetD20_2: D20.2 J1.5 R16.1 | length 513.3
  Bottom Layer w6: 673.46,767.83 ccw(c654.78,786.5) D20.2@681.19,786.5 ; 678.59,772.96 cw(c690,761.55) D20.2@690,777.68 ; D20.2@691.06,785.43 665.34,759.71 665.34,694.53 680.87,679 830,679 852.05,656.95 J1.5@852.05,580.55 ; J1.5@844.43,609.83 ccw(c826.02,628.23) 852.05,628.23 ccw(c878.07,628.23) J1.5@859.67,609.83
  Bottom Layer w20: D20.2@690,786.5 R16.1@690,845.31
NetDEBUG_A5: DEBUG.A5 R24.1 | length 207.8
  Top Layer w6: v1(1574.58,238.09) 1600.91,264.41 DEBUG.A5@1600.91,298.22 ; v1@1574.58,243.95 ccw(c1574.58,258.09) 1584.58,248.09 ccw(c1594.58,238.09) v1@1580.44,238.09 ; DEBUG.A5@1598.85,273.72 cw(c1593.89,268.76) 1600.91,268.76 cw(c1607.92,268.76) DEBUG.A5@1602.96,273.72
  Bottom Layer w6: R24.1@1567.35,212.01 ccw(c1549.9,229.46) v1@1574.58,229.46 ; v1@1569.8,234.71 cw(c1556.28,225.14) 1572.28,220.86 ; v1@1570.44,233.95 cw(c1560.44,223.95) 1574.58,223.95 cw(c1588.73,223.95) v1@1578.72,233.95 ; 1574.47,229.06 cw(c1580.77,227.37) v1@1577.51,233.02 ; 1574.58,224.63 ccw(c1592.44,224.63) R24.1@1579.81,212.01 ; v1(1574.58,238.09) 1574.58,210.33 R24.1@1574.92,209.99
NetDEBUG_B5: DEBUG.B5 R23.1 | length 189.4
  Top Layer w6: v1@1715.44,243.23 ccw(c1706.81,251.86) 1719.02,251.86 ; DEBUG.B5@1716.96,273.72 cw(c1712,268.76) 1719.02,268.76 cw(c1726.03,268.76) DEBUG.B5@1721.07,273.72 ; 1719.02,254.6 ccw(c1735.09,254.6) v1@1723.72,243.23 ; DEBUG.B5@1719.02,298.22 1719.02,239.66 v1(1719.58,239.09)
  Bottom Layer w6: v1@1715.44,234.95 cw(c1705.44,224.95) 1719.58,224.95 cw(c1733.73,224.95) v1@1723.72,234.95 ; v1(1719.58,239.09) 1719.58,224.78 R23.1@1738.58,205.78 ; R23.1@1729.77,205.78 ccw(c1708.5,205.78) 1723.54,220.82 ccw(c1738.58,235.86) R23.1@1738.58,214.59
NetKEY1_1: KEY1.1 KEY1.2 R40.2 | length 502.4
  Top Layer w6: R40.2@1469.01,591.53 ccw(c1453.96,606.57) 1475.24,606.57 ccw(c1496.51,606.57) R40.2@1481.47,591.53 ; R40.2@1472.1,593.54 ccw(c1470.36,598.09) 1475.24,598.09 ; R40.2@1478.37,593.54 cw(c1480.11,598.09) 1475.24,598.09 ; v1@1498.72,652.09 cw(c1484.58,652.09) 1494.58,642.09 cw(c1504.58,632.09) v1@1504.58,646.23 ; v1(1504.58,652.09) 1475.24,622.74 1475.24,598.09
  Bottom Layer w6: KEY1.1@1489.62,756.15 ccw(c1471.22,774.56) 1497.25,774.56 ccw(c1523.27,774.56) KEY1.1@1504.87,756.15 ; KEY1.2@1489.62,894.45 cw(c1471.22,876.05) 1497.25,876.05 cw(c1523.27,876.05) KEY1.2@1504.87,894.45 ; KEY1.2@1497.25,913.89 KEY1.1@1497.25,736.72 1504.58,729.38 v1(1504.58,652.09) ; v1@1500.44,656.23 ccw(c1490.44,666.23) 1504.58,666.23 ccw(c1518.73,666.23) v1@1508.72,656.23
NetL1_1: L1.1 U1.3
NetLED1_2: LED1.2 R28.2 | length 102.1
  Top Layer w10: LED1.2@1494.92,773.65 1494.92,774.99 R28.2@1534.92,814.99 ; LED1.2@1494.92,780.46 ccw(c1494.92,793.67) LED1.2@1504.26,784.33 ; LED1.2@1499.76,775.62 cw(c1509.94,775.62) LED1.2@1502.74,782.81 ; R28.2@1528.11,814.99 cw(c1511.67,814.99) 1523.29,803.36 cw(c1534.92,791.73) R28.2@1534.92,808.18
NetLED2_2: LED2.2 R29.2 | length 92.9
  Top Layer w10: R29.2@1854.61,620.3 LED2.2@1903.27,620.3 ; R29.2@1859.42,615.49 cw(c1871.05,603.86) 1871.05,620.3 cw(c1871.05,636.75) R29.2@1859.42,625.12 ; LED2.2@1897.87,616.88 ccw(c1889.61,608.61) 1889.61,620.3 ccw(c1889.61,631.99) LED2.2@1897.87,623.73
NetM1_60: M1.60 R4.1 | length 169.2
  Top Layer w8: M1.60@1373.57,2364.86 ccw(c1350.15,2388.27) 1383.27,2388.27 ccw(c1416.38,2388.27) M1.60@1392.97,2364.86 ; R4.1@1376.48,2414.79 cw(c1360.08,2398.4) 1383.27,2398.4 ; M1.60@1383.27,2333.5 1383.27,2418.58 R4.1@1385,2420.31 ; 1383.27,2404.52 cw(c1397.8,2404.52) R4.1@1387.52,2414.79
NetM1_89: M1.89 R3.2 | length 216.9
  Top Layer w6: R3.2@594.69,1440 595.47,1439.21 M1.89@688.98,1439.21 ; R3.2@600.92,1433.77 cw(c614.06,1420.63) 614.06,1439.21 ; R3.2@600.92,1446.23 ccw(c617.86,1463.17) 617.86,1439.21 ; M1.89@656.92,1428.81 ccw(c631.79,1403.68) 631.79,1439.21 ccw(c631.79,1474.74) M1.89@656.92,1449.62 ; M1.89@661.16,1433.05 ccw(c646.28,1418.17) 646.28,1439.21 ccw(c646.28,1460.26) M1.89@661.16,1445.38
NetR5_1: R5.1 U1.1 | length 99.1
  Top Layer w20: U1.1@2154.6,443.31 cw(c2156.04,416.03) 2175.35,435.35 ; U1.1@2154.61,456.08 2175.35,435.35 ; R5.1@2222.21,435.35 2175.35,435.35
NetR25_1: R25.1 U3.5 | length 113.2
  Top Layer w6.69: R25.1@1668.94,465.97 ccw(c1659.62,475.29) 1672.8,475.29 ; 1672.8,485.56 ccw(c1700.49,485.56) R25.1@1680.91,465.97 ; U3.5@1672.8,540.17 1672.8,462.11 R25.1@1674.92,459.99
NetR26_1: R26.1 U3.4 | length 121.4
  Top Layer w6.69: R26.1@1634.92,459.99 1657.05,482.11 U3.4@1657.05,540.17 ; R26.1@1634.92,468.45 ccw(c1634.92,488.89) 1649.37,474.44 ccw(c1663.82,459.99) R26.1@1643.39,459.99
PB4: J4.37 M1.66 | length 2015.4
  Top Layer w6: M1.66@1072.86,2301.44 cw(c1047.74,2276.32) 1083.27,2276.32 cw(c1118.8,2276.32) M1.66@1093.67,2301.44 ; M1.66@1077.1,2305.69 cw(c1062.22,2290.81) 1083.27,2290.81 cw(c1104.31,2290.81) M1.66@1089.43,2305.69 ; M1.66@1083.27,2333.5 1083.27,2217.82 1273.09,2028 v1(1780,2028) ; v1@1775.86,2023.86 ccw(c1765.86,2013.86) 1765.86,2028 ccw(c1765.86,2042.14) v1@1775.86,2032.14
  Bottom Layer w6: v1@1775.86,2032.14 ccw(c1765.86,2042.14) 1780,2042.14 ccw(c1794.14,2042.14) v1@1784.14,2032.14 ; v1(1780,2028) 1780,2079 1859,2158 2616.27,2158 J4.37@2666.54,2208.27
PB5: J4.36 M1.65 | length 1974.9
  Top Layer w6: M1.65@1122.86,2301.44 cw(c1097.74,2276.32) 1133.27,2276.32 cw(c1168.8,2276.32) M1.65@1143.67,2301.44 ; M1.65@1127.1,2305.69 cw(c1112.22,2290.81) 1133.27,2290.81 cw(c1154.31,2290.81) M1.65@1139.43,2305.69 ; M1.65@1133.27,2333.5 1133.27,2184.79 1278.06,2040 1755,2040 1764,2049 v1@1795,2049 ; v1@1794.86,2044.86 ccw(c1784.86,2034.86) 1784.86,2049 ccw(c1784.86,2063.14) v1@1794.86,2053.14
  Bottom Layer w6: v1@1794.86,2053.14 ccw(c1784.86,2063.14) 1799,2063.14 ccw(c1813.14,2063.14) v1@1803.14,2053.14 ; v1(1799,2049) 1799,2081.03 1863.97,2146 2528.8,2146 ; J4.36@2538.58,2113.81 ccw(c2503.55,2120.75) 2528.8,2146 ; J4.36@2544.47,2112.64 ccw(c2516.81,2118.12) 2536.75,2138.05 ccw(c2556.68,2157.99) J4.36@2562.16,2130.33 ; J4.36@2561,2136.22 cw(c2554.06,2171.25) 2528.8,2146 ; J4.36@2566.54,2108.27 2528.8,2146
PB6: J4.35 M1.64 | length 2179.5
  Top Layer w6: M1.64@1172.86,2301.44 cw(c1147.74,2276.32) 1183.27,2276.32 cw(c1218.8,2276.32) M1.64@1193.67,2301.44 ; M1.64@1177.1,2305.69 cw(c1162.22,2290.81) 1183.27,2290.81 cw(c1204.31,2290.81) M1.64@1189.43,2305.69 ; M1.64@1183.27,2333.5 1183.27,2151.76 1283.03,2052 1749,2052 1765,2068 1817,2068 v1(1820,2065) ; 1798.61,2068 cw(c1798.61,2043.61) v1@1815.86,2060.86
  Bottom Layer w6: v1@1815.86,2069.14 ccw(c1805.86,2079.14) 1820,2079.14 ccw(c1834.14,2079.14) v1@1824.14,2069.14 ; v1(1820,2065) 1820,2085.06 1868.94,2134 2465,2134 2538,2061 2619.27,2061 ; J4.35@2638.05,2107.68 cw(c2573.91,2106.36) 2619.27,2061 ; J4.35@2644.04,2107.81 cw(c2593.41,2106.76) 2629.22,2070.95 cw(c2665.03,2035.14) J4.35@2666.07,2085.78 ; J4.35@2650.04,2107.93 cw(c2612.92,2107.17) 2639.17,2080.91 cw(c2665.43,2054.65) J4.35@2666.2,2091.78 ; J4.35@2665.95,2079.78 ccw(c2664.63,2015.64) 2619.27,2061 ; J4.35@2666.54,2108.27 2619.27,2061
PB7: J4.33 M1.63 | length 2240.1
  Top Layer w6: M1.63@1222.86,2301.44 cw(c1197.74,2276.32) 1233.27,2276.32 cw(c1268.8,2276.32) M1.63@1243.67,2301.44 ; M1.63@1227.1,2305.69 cw(c1212.22,2290.81) 1233.27,2290.81 cw(c1254.31,2290.81) M1.63@1239.43,2305.69 ; M1.63@1233.27,2333.5 1233.27,2118.73 1288,2064 1741,2064 1762,2085 v1@1845,2085 ; v1@1842.86,2080.86 ccw(c1832.86,2070.86) 1832.86,2085 ccw(c1832.86,2099.14) v1@1842.86,2089.14
  Bottom Layer w6: v1@1845,2085 v1@1846,2086 ; v1(1847,2085) 1884,2122 2460.03,2122 2485,2097.03 2485,1973 2498,1960 2618.27,1960 ; v1@1847,2090.86 ccw(c1847,2105) 1857,2095 ccw(c1867,2085) v1@1852.86,2085 ; J4.33@2638.04,2008.11 cw(c2570.54,2007.73) 2618.27,1960 ; J4.33@2644.04,2008.14 cw(c2590.75,2007.85) 2628.43,1970.17 cw(c2666.11,1932.48) J4.33@2666.41,1985.77 ; J4.33@2650.04,2008.18 cw(c2610.96,2007.96) 2638.6,1980.33 cw(c2666.23,1952.7) J4.33@2666.44,1991.77 ; J4.33@2666.38,1979.77 ccw(c2666,1912.27) 2618.27,1960 ; J4.33@2666.54,2008.27 2618.27,1960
